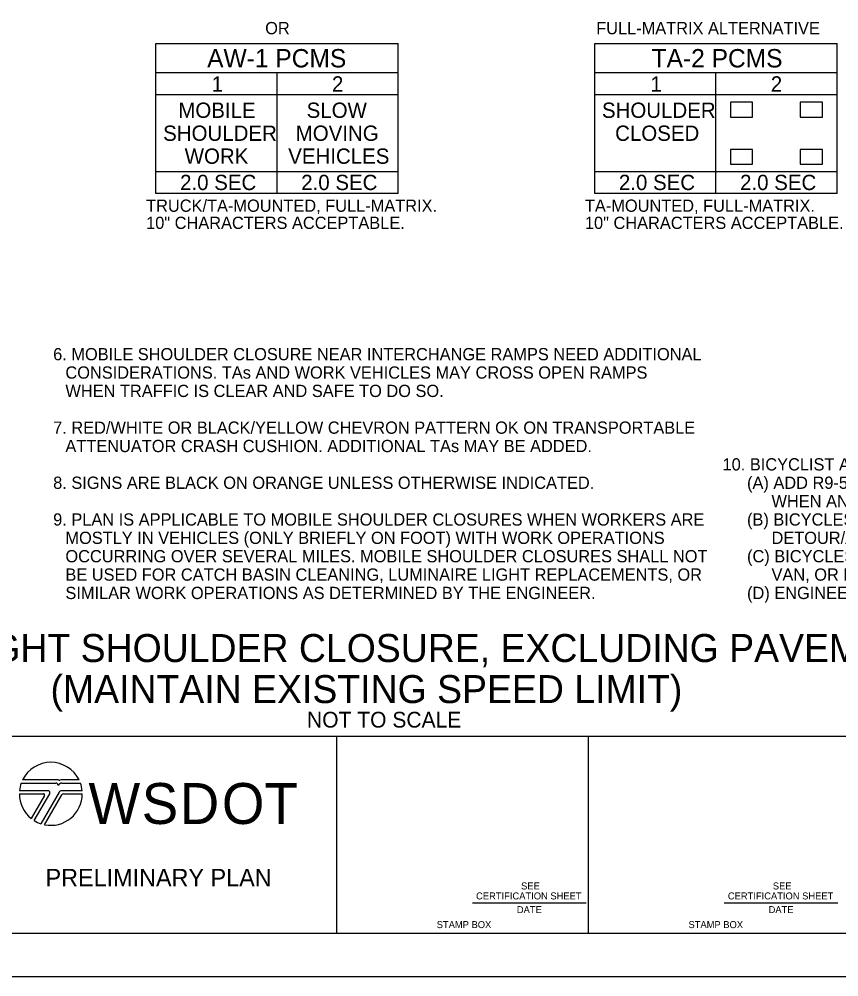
# Model space of a CAD drawing. Extents: x 0 to 17, y 0 to 11.
# Drawn here: x 8.43 to 13.11, y 0 to 5.47 of the extents above; entities that cross this region are included whole.
import ezdxf

# ---------------------------------------------------------------- set-up
doc = ezdxf.new("R2010")
doc.units = 0
for name, color, linetype in [('SH_GI_Logo_WSDOT', 7, 'Continuous'), ('SH_GI_PlotLimits', 7, 'Continuous'), ('SH_GI_SheetBorder1', 7, 'Continuous'), ('SH_GI_SheetBorder3', 7, 'Continuous'), ('SH_GI_SheetTextInCells', 7, 'Continuous'), ('SH_GI_TitleBlockPrelimText', 7, 'Continuous'), ('TR_SN_ConstructionSigns', 7, 'Continuous'), ('TR_WZ_PortableChangeMessageSign', 7, 'Continuous'), ('TR_WZ_WorkZoneTextCurrent', 7, 'Continuous')]:
    doc.layers.add(name, color=color, linetype=linetype)

msp = doc.modelspace()

# ---------------------------------------------------------------- linework, layer by layer
at = {"layer": 'SH_GI_Logo_WSDOT'}
for p, q in [((8.4377, 1.1078), (8.6354, 1.1078)), ((8.6489, 1.1258), (8.4454, 1.1258)), ((8.7684, 1.1258), (8.6653, 1.1258)), ((8.6705, 1.1078), (8.776, 1.1078)), ((8.4269, 1.0463), (8.5657, 1.0463)), ((8.59, 1.0643), (8.4278, 1.0643)), ((8.5121, 0.8933), (8.6004, 1.0463)), ((8.6541, 1.0553), (8.5502, 0.8754)), ((8.5713, 0.8698), (8.6697, 1.0403)), ((8.786, 1.0643), (8.6697, 1.0643)), ((8.6801, 1.0463), (8.7869, 1.0463)), ((8.5709, 1.0373), (8.4948, 0.9054))]:
    msp.add_line(p, q, dxfattribs=at)
for centre, radius, start, end in [((8.6069, 1.0463), 0.18, 26.2103, 153.7897), ((8.6069, 1.0463), 0.18, 160.0216, 174.2608), ((8.6354, 1.0943), 0.0135, 360, 90), ((8.6489, 1.1198), 0.006, 0, 90), ((8.6705, 1.0838), 0.024, 90, 154.0555), ((8.6653, 1.1138), 0.012, 90, 150), ((8.6069, 1.0463), 0.18, 5.7392, 19.9784), ((8.6069, 1.0463), 0.18, 180, 231.4963), ((8.5657, 1.0403), 0.006, 330, 90), ((8.6069, 1.0463), 0.18, 258.5899, 0), ((8.59, 1.0523), 0.012, 330, 90), ((8.6697, 1.0463), 0.018, 90, 150), ((8.6801, 1.0343), 0.012, 90, 150), ((8.6069, 1.0463), 0.18, 238.2117, 251.6613)]:
    msp.add_arc(centre, radius, start, end, dxfattribs=at)
at = {"layer": 'SH_GI_PlotLimits'}
msp.add_lwpolyline([(0, 11), (17, 11), (17, 0), (0, 0)], close=True, dxfattribs=at)
at = {"layer": 'SH_GI_SheetBorder1'}
for p, q in [((11.0184, 0.4233), (11.6683, 0.4233)), ((12.4584, 0.4233), (13.1083, 0.4233))]:
    msp.add_line(p, q, dxfattribs=at)
at = {"layer": 'SH_GI_SheetBorder3'}
for p, q in [((1, 1.375), (16.75, 1.375)), ((10.24, 1.375), (10.24, 0.25)), ((11.68, 1.3759), (11.68, 0.25)), ((1, 0.25), (16.75, 0.25))]:
    msp.add_line(p, q, dxfattribs=at)
at = {"layer": 'TR_WZ_PortableChangeMessageSign'}
for p, q in [((9.2079, 5.3353), (10.5939, 5.3353)), ((9.2079, 4.4785), (9.2079, 5.3353)), ((10.5939, 4.4785), (10.5939, 5.3353)), ((11.7178, 5.3353), (13.1038, 5.3353)), ((11.7178, 4.4785), (11.7178, 5.3353)), ((13.1038, 4.4785), (13.1038, 5.3353)), ((10.5939, 5.1673), (9.2079, 5.1673)), ((9.9009, 4.4785), (9.9009, 5.1673)), ((13.1038, 5.1673), (11.7178, 5.1673)), ((12.4108, 4.4785), (12.4108, 5.1673)), ((9.9009, 5.0413), (9.2079, 5.0413)), ((10.5939, 5.0413), (9.9009, 5.0413)), ((12.4108, 5.0413), (11.7178, 5.0413)), ((13.1038, 5.0413), (12.4108, 5.0413)), ((9.2079, 4.6045), (9.9009, 4.6045)), ((9.9009, 4.6045), (10.5939, 4.6045)), ((11.7178, 4.6045), (12.4108, 4.6045)), ((12.4108, 4.6045), (13.1038, 4.6045)), ((10.5939, 4.4785), (9.2079, 4.4785)), ((13.1038, 4.4785), (11.7178, 4.4785))]:
    msp.add_line(p, q, dxfattribs=at)
for points in [[(12.6208, 4.9993), (12.4948, 4.9993), (12.4948, 4.9153), (12.6208, 4.9153)], [(13.0198, 4.9993), (12.8938, 4.9993), (12.8938, 4.9153), (13.0198, 4.9153)], [(12.6208, 4.7305), (12.4948, 4.7305), (12.4948, 4.6465), (12.6208, 4.6465)], [(13.0198, 4.7305), (12.8938, 4.7305), (12.8938, 4.6465), (13.0198, 4.6465)]]:
    msp.add_lwpolyline(points, close=True, dxfattribs=at)

# ---------------------------------------------------------------- texts
at = {"layer": 'SH_GI_Logo_WSDOT'}
for s, p in [('W', (8.8225, 0.8739)), ('S', (9.1268, 0.8739)), ('D', (9.3442, 0.8739)), ('O', (9.5854, 0.8739)), ('T', (9.8296, 0.8739))]:
    msp.add_text(s, height=0.234, dxfattribs=at).set_placement(p)
at = {"layer": 'SH_GI_SheetTextInCells'}
for s, p in [('SEE', (11.2966, 0.4995)), ('SEE', (12.7366, 0.4995)), ('CERTIFICATION SHEET', (11.0393, 0.4425)), ('CERTIFICATION SHEET', (12.4793, 0.4425)), ('DATE', (11.2723, 0.3641)), ('DATE', (12.7123, 0.3641)), ('STAMP BOX', (10.8141, 0.2786)), ('STAMP BOX', (12.2541, 0.2786))]:
    msp.add_text(s, height=0.04, dxfattribs=at).set_placement(p)
at = {"layer": 'SH_GI_TitleBlockPrelimText'}
msp.add_text('PRELIMINARY PLAN', height=0.1, dxfattribs=at).set_placement((8.5768, 0.5173))
at = {"layer": 'TR_SN_ConstructionSigns'}
for s, p in [('OR', (9.833, 5.3886)), ('FULL-MATRIX ALTERNATIVE', (11.7261, 5.3886))]:
    msp.add_text(s, height=0.07, dxfattribs=at).set_placement(p)
at = {"layer": 'TR_WZ_PortableChangeMessageSign'}
for s, height, p in [('AW-1 PCMS', 0.105, (9.5011, 5.1988)), ('TA-2 PCMS', 0.105, (12.0431, 5.1988)), ('1', 0.0875, (9.527, 5.0605)), ('2', 0.0875, (10.215, 5.0605)), ('1', 0.0875, (12.0369, 5.0605)), ('2', 0.0875, (12.7249, 5.0605)), ('MOBILE', 0.0875, (9.3362, 4.9104)), ('SLOW', 0.0875, (10.0701, 4.9104)), ('SHOULDER', 0.0875, (11.7592, 4.9104)), ('SHOULDER', 0.0875, (9.2494, 4.7791)), ('MOVING', 0.0875, (10.0077, 4.7791)), ('CLOSED', 0.0875, (11.8346, 4.7791)), ('WORK', 0.0875, (9.3727, 4.6479)), ('VEHICLES', 0.0875, (9.9648, 4.6479)), ('2.0 SEC', 0.0875, (9.3462, 4.4977)), ('2.0 SEC', 0.0875, (10.0392, 4.4977)), ('2.0 SEC', 0.0875, (11.8561, 4.4977)), ('2.0 SEC', 0.0875, (12.5491, 4.4977)), ('TRUCK/TA-MOUNTED, FULL-MATRIX.', 0.07, (9.152, 4.3735)), ('TA-MOUNTED, FULL-MATRIX.', 0.07, (11.6618, 4.3735)), ('10" CHARACTERS ACCEPTABLE.', 0.07, (9.152, 4.2755)), ('10" CHARACTERS ACCEPTABLE.', 0.07, (11.6618, 4.2755))]:
    msp.add_text(s, height=height, rotation=360, dxfattribs=at).set_placement(p)
at = {"layer": 'TR_WZ_WorkZoneTextCurrent'}
for s, height, p in [('6. MOBILE SHOULDER CLOSURE NEAR INTERCHANGE RAMPS NEED ADDITIONAL ', 0.07, (8.6204, 3.5247)), ('CONSIDERATIONS. TAs AND WORK VEHICLES MAY CROSS OPEN RAMPS ', 0.07, (8.6904, 3.4197)), ('WHEN TRAFFIC IS CLEAR AND SAFE TO DO SO.', 0.07, (8.6904, 3.3147)), ('7. RED/WHITE OR BLACK/YELLOW CHEVRON PATTERN OK ON TRANSPORTABLE ', 0.07, (8.6204, 3.1047)), ('ATTENUATOR CRASH CUSHION. ADDITIONAL TAs MAY BE ADDED.', 0.07, (8.6904, 2.9997)), ('10. BICYCLIST ACCOMMODATIONS, WHERE FACILITY OPEN TO BICYCLES:', 0.07, (12.449, 2.8947)), ('8. SIGNS ARE BLACK ON ORANGE UNLESS OTHERWISE INDICATED.', 0.07, (8.6204, 2.7897)), ('(A) ADD R9-501 SIGN MOUNTED TO REAR OF ', 0.07, (12.589, 2.7897)), ('WHEN AND WHERE FEASIBLE, LIMIT BICYCLIST DELAYS TO 5 MINUTES.', 0.07, (12.729, 2.6847)), ('9. PLAN IS APPLICABLE TO MOBILE SHOULDER CLOSURES WHEN WORKERS ARE ', 0.07, (8.6204, 2.5797)), ('(B) BICYCLES PROHIBITED VIA W20-2A, R5-601 & R5-6 SIGNS. PROVIDE SIGNED ', 0.07, (12.589, 2.5797)), ('MOSTLY IN VEHICLES (ONLY BRIEFLY ON FOOT) WITH WORK OPERATIONS ', 0.07, (8.6904, 2.4747)), ('DETOUR/ALTERNATIVE ROUTE AROUND LIMITS OF MOBILE SHOULDER CLOSURE.', 0.07, (12.729, 2.4747)), ('OCCURRING OVER SEVERAL MILES. MOBILE SHOULDER CLOSURES SHALL NOT ', 0.07, (8.6904, 2.3697)), ('(C) BICYCLES PROHIBITED VIA R5-6 SIGN(S). PROVIDE FREE SHUTTLE (WORK TRUCK, ', 0.07, (12.589, 2.3697)), ('BE USED FOR CATCH BASIN CLEANING, LUMINAIRE LIGHT REPLACEMENTS, OR ', 0.07, (8.6904, 2.2647)), ('VAN, OR BUS OK) + CONTACT INFORMATION/PHONE BOX/LABORER. ', 0.07, (12.729, 2.2647)), ('SIMILAR WORK OPERATIONS AS DETERMINED BY THE ENGINEER.', 0.07, (8.6904, 2.1597)), ('(D) ENGINEER TO ACCEPT ANY ALTERNATIVE STRATEGIES.', 0.07, (12.589, 2.1597)), ('FREEWAY (2+ LANES): MOBILE RIGHT SHOULDER CLOSURE, EXCLUDING PAVEMENT MARKING OPERATIONS', 0.16, (4.8007, 1.7997)), ('(MAINTAIN EXISTING SPEED LIMIT)', 0.16, (8.6051, 1.565)), ('NOT TO SCALE', 0.09, (10.0722, 1.425))]:
    msp.add_text(s, height=height, rotation=360, dxfattribs=at).set_placement(p)

doc.saveas('drawing.dxf')
